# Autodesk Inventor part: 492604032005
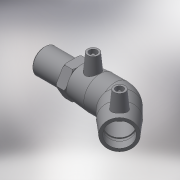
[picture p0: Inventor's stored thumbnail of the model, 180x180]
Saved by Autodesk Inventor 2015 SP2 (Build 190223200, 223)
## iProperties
Created: 2017-06
Part Number: 492604032005
Material: Generic
Description: PLASSON 45° ELBOW TRANSITION MALE 32-1/2"
Document SubType Name: Modeling
Designer: KIM
Mass: 106.426 g
Surface Area: 319.25 cm^2
Volume: 106.426 cm^3
Density: 1 g/cm^3
Appearance: Default
Author: KIM
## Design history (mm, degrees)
derived "492604.ipt"
feature "Solid1::492604.ipt"
tag "TaggingFeature1"
body "Solid1"
other parameters: "d2" = 44, "d4" = 23.75, "d5" = 39.6, "d8" = 168 deg, "d10" = 15.6, "d11" = 5.2, "d29" = 43, "d30" = 15, "d31" = 33.25, "d34" = 5 deg, "d41" = 4, "d42" = 14, "d43" = 0, "d49" = 32, "d50" = 20.8, "d51" = 15.6, "d52" = 40.17, "d54" = 135 deg, "d86" = 19.8, "d87" = 135 deg, "d88" = 95, "d90" = 39, "d91" = 0, "d92" = 39, "d93" = 0, "d101" = 3, "d102" = 0, "d107" = 0.1, "d108" = 23, "d109" = 20.955, "d110" = 29, "d111" = 7.25, "d112" = 44, "d113" = 14.6685, "d114" = 26.1, "d116" = 1.32, "d122" = 0, "d123" = 1.04775, "d_" = 32, "L_" = 124, "L_1" = 39, "D_" = 23, "A_" = 43, "d_2" = 12, "L_2" = 29, "R_" = 20.955, "D_1" = 44
